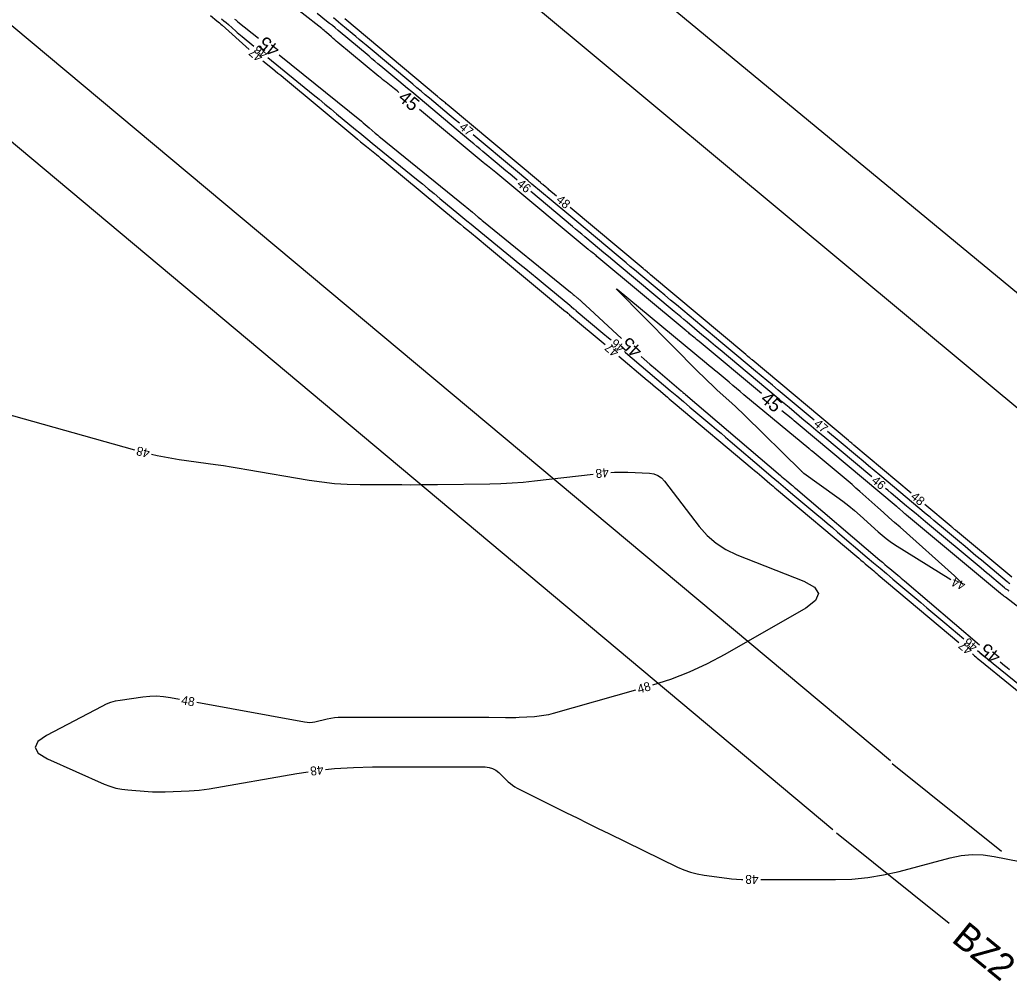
# Model space of a CAD drawing. Extents: x 2384780 to 2405861, y 547869 to 573706.
# Drawn here: x 2392529.2 to 2392751.8, y 552907.6 to 553123.7 of the extents above; entities that cross this region are included whole.
import ezdxf

# ---------------------------------------------------------------- set-up
doc = ezdxf.new("R2010")
doc.units = 0
for name, color, linetype in [('Old_Level_60', 7, 'Continuous'), ('Old_Level_61', 7, 'Continuous'), ('Prop Buffer Zone 1', 7, 'Continuous'), ('Prop Buffer Zone 2', 7, 'Continuous')]:
    doc.layers.add(name, color=color, linetype=linetype)

msp = doc.modelspace()

# ---------------------------------------------------------------- linework, layer by layer
at = {"layer": 'Old_Level_60'}
for points in [[(2392572.113, 553124.66375), (2392573.5235, 553123.49125), (2392573.8245, 553123.2385), (2392574.1235, 553122.9835), (2392574.42025, 553122.72575), (2392574.7145, 553122.4655), (2392580.7955, 553117.043), (2392580.8155, 553117.02525)], [(2392574.6105, 553123.9415), (2392575.1245, 553123.5025), (2392575.63475, 553123.05925), (2392576.14125, 553122.61175), (2392577.7895, 553121.142), (2392578.14425, 553120.829), (2392578.50275, 553120.52025), (2392578.8645, 553120.2155), (2392579.23, 553119.91475), (2392581.874, 553117.76375)], [(2392641.1105, 553087.631), (2392640.4955, 553088.145), (2392639.51825, 553088.96175), (2392638.54125, 553089.7785), (2392637.5645, 553090.59575), (2392636.588, 553091.413), (2392633.39775, 553094.08325), (2392632.714, 553094.65525), (2392632.03025, 553095.22725), (2392631.3465, 553095.79925), (2392630.6625, 553096.37075), (2392617.3725, 553107.4775), (2392616.41825, 553108.27525), (2392615.464, 553109.073), (2392614.51, 553109.871), (2392613.55625, 553110.66925), (2392610.4405, 553113.27725), (2392609.77275, 553113.836), (2392609.105, 553114.3945), (2392608.437, 553114.953), (2392607.769, 553115.5115), (2392600.80925, 553121.32775), (2392600.17225, 553121.85675), (2392599.532, 553122.382), (2392598.88875, 553122.9035), (2392598.24225, 553123.421), (2392596.12525, 553125.10525)], [(2392628.10725, 553100.43), (2392627.137, 553101.2415), (2392625.787, 553102.36975), (2392621.3765, 553106.05575), (2392620.4315, 553106.84575), (2392619.4865, 553107.636), (2392618.54175, 553108.42625), (2392617.59725, 553109.21675), (2392607.14, 553117.96925), (2392606.3545, 553118.6265), (2392605.56875, 553119.28375), (2392604.783, 553119.941), (2392603.99725, 553120.59775), (2392601.42975, 553122.7435), (2392600.878, 553123.2015), (2392600.32375, 553123.6565), (2392599.76675, 553124.10775)], [(2392649.97075, 553084.05325), (2392648.23725, 553085.504), (2392648.04625, 553085.664), (2392647.855, 553085.824), (2392647.66375, 553085.98375), (2392647.4725, 553086.14375), (2392646.84775, 553086.666), (2392646.71375, 553086.77775), (2392646.58, 553086.88975), (2392646.446, 553087.00175), (2392646.31225, 553087.11375), (2392625.3745, 553104.6385), (2392625.1595, 553104.81875), (2392624.94425, 553104.99875), (2392624.729, 553105.17875), (2392624.5135, 553105.35875), (2392623.81025, 553105.9465), (2392623.6595, 553106.0725), (2392623.50875, 553106.1985), (2392623.35825, 553106.3245), (2392623.2075, 553106.4505), (2392602.30675, 553123.94425)], [(2392584.97675, 553115.2395), (2392595.2065, 553106.9175), (2392596.52775, 553105.84), (2392597.84625, 553104.759), (2392599.16225, 553103.67475), (2392600.47525, 553102.58725), (2392604.7605, 553099.0295), (2392605.67975, 553098.26825), (2392606.60075, 553097.50925), (2392607.524, 553096.75275), (2392608.44875, 553095.99825), (2392618.4575, 553087.8565), (2392619.77275, 553086.784), (2392621.0855, 553085.70775), (2392622.3955, 553084.6285), (2392623.70275, 553083.546), (2392627.9685, 553080.004), (2392628.8835, 553079.24625), (2392629.8005, 553078.49075), (2392630.7195, 553077.7375), (2392631.64025, 553076.98675), (2392641.70975, 553068.796), (2392643.019, 553067.72825), (2392644.32575, 553066.65725), (2392645.62975, 553065.58275), (2392646.931, 553064.50525), (2392652.93825, 553059.51725), (2392652.96775, 553059.49275), (2392652.997, 553059.46825), (2392653.02625, 553059.44375), (2392653.0555, 553059.41925), (2392653.151, 553059.339), (2392653.1715, 553059.322), (2392653.19175, 553059.30475), (2392653.21225, 553059.28725), (2392653.2325, 553059.27), (2392653.86075, 553058.733), (2392653.9955, 553058.618), (2392654.1305, 553058.5035), (2392654.26575, 553058.389), (2392654.40125, 553058.275), (2392660.37625, 553053.25575), (2392661.6555, 553052.179), (2392662.20525, 553051.7145)], [(2392583.902, 553114.48125), (2392586.02125, 553112.757), (2392586.649, 553112.245), (2392587.2755, 553111.7315), (2392587.90075, 553111.21625), (2392588.52475, 553110.6995), (2392604.5465, 553097.3975), (2392605.21675, 553096.84225), (2392605.8885, 553096.28875), (2392606.5615, 553095.737), (2392607.236, 553095.187), (2392609.44175, 553093.39275), (2392609.914, 553093.00775), (2392610.385, 553092.6215), (2392610.85525, 553092.234), (2392611.3245, 553091.8455), (2392627.66775, 553078.276), (2392628.33675, 553077.722), (2392629.007, 553077.16975), (2392629.6785, 553076.61925), (2392630.3515, 553076.07025), (2392632.5525, 553074.28025), (2392633.0235, 553073.896), (2392633.49375, 553073.5105), (2392633.96275, 553073.124), (2392634.431, 553072.73625), (2392651.996, 553058.152), (2392652.05925, 553058.0995), (2392652.12225, 553058.047), (2392652.18525, 553057.99425), (2392652.248, 553057.9415), (2392652.454, 553057.7685), (2392652.4975, 553057.73175), (2392652.541, 553057.695), (2392652.5845, 553057.65825), (2392652.62775, 553057.62125), (2392652.769, 553057.5005), (2392652.79925, 553057.47475), (2392652.8295, 553057.449), (2392652.86, 553057.42325), (2392652.8905, 553057.39775), (2392660.89675, 553050.672)], [(2392707.87475, 553033.69825), (2392699.7985, 553040.45825), (2392698.5195, 553041.52875), (2392697.24, 553042.599), (2392695.9605, 553043.66875), (2392694.68075, 553044.7385), (2392690.50025, 553048.2325), (2392689.60425, 553048.9815), (2392688.70875, 553049.73025), (2392687.81325, 553050.4795), (2392686.91775, 553051.22875), (2392676.928, 553059.5905), (2392675.6255, 553060.6805), (2392674.32275, 553061.77025), (2392673.01975, 553062.86), (2392671.7165, 553063.94925), (2392667.459, 553067.50725), (2392666.54675, 553068.26975), (2392665.63475, 553069.0325), (2392664.72275, 553069.79525), (2392663.811, 553070.5585), (2392654.05725, 553078.7225), (2392652.73125, 553079.83225), (2392651.405, 553080.9415), (2392650.0785, 553082.05075), (2392648.752, 553083.15975), (2392644.418, 553086.78175), (2392643.48925, 553087.558), (2392642.56075, 553088.33425), (2392641.6325, 553089.111), (2392640.70425, 553089.88775), (2392631.186, 553097.8545), (2392631.17525, 553097.8635)], [(2392720.89825, 553020.92325), (2392709.8635, 553030.14525), (2392708.818, 553031.0195), (2392707.7725, 553031.8935), (2392706.72725, 553032.768), (2392705.682, 553033.64275), (2392702.26825, 553036.5), (2392701.53675, 553037.11225), (2392700.805, 553037.7245), (2392700.07325, 553038.3365), (2392699.34125, 553038.94825), (2392686.741, 553049.47875), (2392685.71825, 553050.33375), (2392684.6955, 553051.189), (2392683.67325, 553052.04425), (2392682.65075, 553052.89975), (2392679.31175, 553055.69475), (2392678.596, 553056.2935), (2392677.8805, 553056.89225), (2392677.1645, 553057.49075), (2392676.44875, 553058.08925), (2392663.61825, 553068.812), (2392662.61825, 553069.648), (2392661.6185, 553070.484), (2392660.619, 553071.32), (2392659.6195, 553072.1565), (2392656.35475, 553074.889), (2392655.65525, 553075.4745), (2392654.9555, 553076.05975), (2392654.25575, 553076.645), (2392653.55575, 553077.23), (2392644.17975, 553085.06575)], [(2392729.72275, 553017.30275), (2392716.8235, 553028.09975), (2392716.7045, 553028.19925), (2392716.5855, 553028.29875), (2392716.46675, 553028.39825), (2392716.3475, 553028.49775), (2392715.95875, 553028.82275), (2392715.8755, 553028.89225), (2392715.79225, 553028.962), (2392715.709, 553029.03175), (2392715.62575, 553029.10125), (2392693.96175, 553047.2345), (2392693.81875, 553047.35425), (2392693.67575, 553047.474), (2392693.5325, 553047.59375), (2392693.3895, 553047.71325), (2392692.922, 553048.104), (2392692.82175, 553048.18775), (2392692.7215, 553048.2715), (2392692.6215, 553048.35525), (2392692.52125, 553048.43925), (2392671.09975, 553066.36925), (2392670.93275, 553066.50925), (2392670.7655, 553066.649), (2392670.59825, 553066.78875), (2392670.431, 553066.9285), (2392669.88475, 553067.38525), (2392669.76775, 553067.483), (2392669.65075, 553067.58075), (2392669.53375, 553067.67875), (2392669.41675, 553067.7765), (2392653.038, 553081.48575)], [(2392741.396, 552996.756), (2392741.228, 552997.003), (2392739.46225, 552998.67075), (2392727.218, 553009.59675), (2392725.9755, 553010.7055), (2392724.733, 553011.81425), (2392723.4905, 553012.923), (2392722.248, 553014.03175), (2392718.189, 553017.6535), (2392717.316, 553018.426), (2392716.43675, 553019.19125), (2392715.55125, 553019.949), (2392714.65925, 553020.6995), (2392707.456, 553026.71025), (2392707.384, 553026.77025), (2392707.312, 553026.83), (2392707.24, 553026.89), (2392707.16775, 553026.94975), (2392706.93225, 553027.14475), (2392706.88175, 553027.18675), (2392706.83125, 553027.2285), (2392706.78075, 553027.27025), (2392706.73025, 553027.312), (2392692.10825, 553039.42125), (2392691.273, 553040.1135), (2392690.43825, 553040.80675), (2392689.60425, 553041.5005), (2392688.771, 553042.19525), (2392686.04975, 553044.46575), (2392685.46625, 553044.95175), (2392684.88225, 553045.4375), (2392684.29775, 553045.92225), (2392683.71275, 553046.4065), (2392663.59025, 553063.03825), (2392663.587, 553063.04075), (2392663.584, 553063.0435), (2392663.58075, 553063.046), (2392663.57775, 553063.0485), (2392663.5675, 553063.05725), (2392663.56525, 553063.059), (2392663.563, 553063.06075), (2392663.56075, 553063.0625), (2392663.55875, 553063.06425), (2392663.42125, 553063.1725), (2392663.399, 553063.18975), (2392663.3915, 553063.195), (2392663.39825, 553063.1885), (2392663.4195, 553063.17025)], [(2392663.4195, 553063.17025), (2392663.559, 553063.05125), (2392663.55925, 553063.051), (2392663.55925, 553063.051), (2392663.5595, 553063.05075), (2392663.55975, 553063.0505), (2392663.56025, 553063.05), (2392663.5605, 553063.05), (2392663.5605, 553063.04975), (2392663.56075, 553063.04975), (2392663.56075, 553063.0495), (2392663.577, 553063.03475), (2392663.58025, 553063.0315), (2392663.58375, 553063.02825), (2392663.587, 553063.025), (2392663.5905, 553063.02175), (2392681.99425, 553044.393), (2392682.987, 553043.40275), (2392683.9935, 553042.427), (2392685.014, 553041.466), (2392686.0485, 553040.51975), (2392689.45075, 553037.452), (2392690.17625, 553036.79075), (2392690.89425, 553036.12175), (2392691.60475, 553035.445), (2392692.308, 553034.76025), (2392704.95075, 553022.3175), (2392705.0095, 553022.25975), (2392705.068, 553022.202), (2392705.12675, 553022.14425), (2392705.18525, 553022.0865), (2392705.377, 553021.898), (2392705.41875, 553021.8585), (2392705.462, 553021.82075), (2392705.50675, 553021.78475), (2392705.553, 553021.75075), (2392713.0355, 553016.46075), (2392714.387, 553015.4735), (2392715.70575, 553014.446), (2392716.99225, 553013.37775), (2392718.246, 553012.269), (2392722.2885, 553008.5815), (2392723.17075, 553007.8125), (2392724.08525, 553007.086), (2392725.032, 553006.402), (2392726.011, 553005.7605), (2392738.65725, 552997.8765)], [(2392665.25475, 553049.12575), (2392665.4805, 553048.9335), (2392674.00475, 553041.657), (2392675.49275, 553040.38975), (2392676.983, 553039.12525), (2392678.47575, 553037.86375), (2392679.97125, 553036.60525), (2392684.86, 553032.499), (2392685.907, 553031.618), (2392686.952, 553030.73525), (2392687.9955, 553029.8505), (2392689.0375, 553028.96375), (2392696.602, 553022.51425), (2392698.22425, 553021.1335), (2392699.84925, 553019.756), (2392701.4765, 553018.38175), (2392703.1065, 553017.01025), (2392708.52475, 553012.46025), (2392709.68475, 553011.48425), (2392710.84325, 553010.506), (2392712, 553009.526), (2392713.15525, 553008.544), (2392719.854, 553002.838), (2392721.29075, 553001.61675), (2392722.72925, 553000.39775), (2392724.17025, 552999.1815), (2392725.61325, 552997.9675), (2392731.92725, 552992.666), (2392733.27925, 552991.52875), (2392734.6295, 552990.38925), (2392735.97775, 552989.24775), (2392737.32425, 552988.10375), (2392741.563, 552984.49675)], [(2392663.9595, 553048.099), (2392670.36525, 553042.718), (2392670.99025, 553042.19175), (2392671.61425, 553041.6645), (2392672.23725, 553041.13575), (2392672.85925, 553040.606), (2392674.8895, 553038.873), (2392675.32475, 553038.502), (2392675.761, 553038.132), (2392676.19775, 553037.763), (2392676.6355, 553037.3945), (2392693.9575, 553022.84575), (2392694.50675, 553022.3835), (2392695.055, 553021.9205), (2392695.6025, 553021.45625), (2392696.149, 553020.99125), (2392697.933, 553019.47), (2392698.31575, 553019.1445), (2392698.699, 553018.8195), (2392699.08275, 553018.4955), (2392699.46725, 553018.172), (2392717.47575, 553003.04875), (2392717.9585, 553002.64275), (2392718.44025, 553002.23575), (2392718.9215, 553001.82825), (2392719.402, 553001.41975), (2392720.97025, 553000.08375), (2392721.30675, 552999.79775), (2392721.6435, 552999.5125), (2392721.98075, 552999.22775), (2392722.31875, 552998.9435), (2392740.46675, 552983.705)], [(2392525.41825, 553035.3715), (2392554.98525, 553027.0115)], [(2392751.8935, 552996.914), (2392751.70325, 552997.051), (2392751.51725, 552997.1935), (2392751.33525, 552997.3415), (2392745.5385, 553002.19375), (2392744.30625, 553003.22475), (2392743.074, 553004.25575), (2392741.8415, 553005.28625), (2392740.60875, 553006.31675), (2392736.58175, 553009.6825), (2392735.71875, 553010.40375), (2392734.856, 553011.12525), (2392733.9935, 553011.84675), (2392733.131, 553012.5685), (2392722.66875, 553021.326), (2392721.413, 553022.37675), (2392720.15725, 553023.42725), (2392718.90125, 553024.47775), (2392717.645, 553025.52775), (2392713.541, 553028.95775), (2392712.66175, 553029.69275), (2392711.7825, 553030.428), (2392710.94225, 553031.13075)], [(2392558.86175, 553026.0275), (2392560.0825, 553025.7485), (2392562.56625, 553025.269), (2392565.0675, 553024.8735), (2392573.2675, 553023.719), (2392575.02375, 553023.465), (2392576.77775, 553023.198), (2392578.52975, 553022.91775), (2392580.27975, 553022.6245), (2392594.3275, 553020.21675), (2392597.169, 553019.79025), (2392600.02075, 553019.48225), (2392602.88275, 553019.2935), (2392605.755, 553019.2235), (2392615.155, 553019.18875), (2392617.16925, 553019.18575), (2392619.1835, 553019.1915), (2392621.19775, 553019.206), (2392623.21175, 553019.22925), (2392634.943, 553019.3905), (2392637.45475, 553019.45675), (2392639.9625, 553019.58625), (2392642.466, 553019.77925), (2392644.96575, 553020.03575), (2392658.213, 553021.56375)], [(2392662.19325, 553021.9515), (2392662.998, 553021.99575), (2392664.49, 553022.018), (2392665.98375, 553021.9805), (2392670.86725, 553021.7605), (2392671.8625, 553021.6155), (2392672.7555, 553021.274), (2392673.546, 553020.7365), (2392674.234, 553020.003), (2392682.03875, 553009.81175), (2392683.82175, 553007.7745), (2392685.82625, 553006.03025), (2392688.05225, 553004.57925), (2392690.4995, 553003.4215), (2392705.563, 552997.4665), (2392708.011, 552996.13375), (2392708.89975, 552994.68825), (2392708.22875, 552993.1295), (2392705.9985, 552991.458), (2392687.7995, 552981.0095), (2392683.84675, 552978.89625), (2392679.788, 552977.034), (2392675.623, 552975.4225), (2392671.55875, 552974.12825)], [(2392751.785, 552995.25025), (2392751.6505, 552995.34425), (2392751.51425, 552995.43575), (2392751.066, 552995.73), (2392750.97075, 552995.7945), (2392750.87775, 552995.86175), (2392750.7865, 552995.9315), (2392750.6975, 552996.00375), (2392747.86675, 552998.37325), (2392747.26, 552998.881), (2392746.6535, 552999.3885), (2392746.0465, 552999.896), (2392745.43975, 553000.40325), (2392732.986, 553010.8115), (2392731.9175, 553011.70475), (2392730.84925, 553012.598), (2392729.781, 553013.4915), (2392728.71325, 553014.3855), (2392725.22475, 553017.3055), (2392724.477, 553017.931), (2392723.967, 553018.3575)], [(2392752.34825, 552998.36475), (2392739.685, 553008.96475), (2392739.59, 553009.044), (2392739.49525, 553009.1235), (2392739.40025, 553009.20275), (2392739.3055, 553009.282), (2392738.9955, 553009.541), (2392738.92925, 553009.5965), (2392738.86275, 553009.65225), (2392738.79625, 553009.70775), (2392738.73, 553009.76325), (2392732.79, 553014.73525)], [(2392744.614, 552981.91), (2392745.63075, 552981.05975), (2392746.89025, 552980.01925), (2392748.1555, 552978.986), (2392756.01225, 552972.608)], [(2392743.5205, 552981.1215), (2392744.0025, 552980.71125), (2392744.2985, 552980.46075), (2392744.59575, 552980.21225), (2392744.8945, 552979.96525), (2392745.19475, 552979.72), (2392765.6355, 552963.1265)], [(2392667.71425, 552973.02375), (2392649.216, 552967.7415), (2392648.17925, 552967.4755), (2392647.1325, 552967.267), (2392646.076, 552967.116), (2392645.00975, 552967.02225), (2392641.51025, 552966.81025), (2392640.76025, 552966.77225), (2392640.01, 552966.74925), (2392639.25925, 552966.741), (2392638.5085, 552966.7475), (2392634.75925, 552966.8175), (2392633.956, 552966.8305), (2392633.1525, 552966.84), (2392632.349, 552966.8455), (2392631.5455, 552966.8475), (2392601.70975, 552966.8475), (2392600.85775, 552966.823), (2392600.01125, 552966.75), (2392599.1705, 552966.62825), (2392598.33525, 552966.458), (2392595.616, 552965.822), (2392595.03275, 552965.716), (2392594.44775, 552965.67125), (2392593.86125, 552965.6875), (2392593.2735, 552965.76475), (2392569.05325, 552970.199)], [(2392565.11875, 552970.91925), (2392563.10225, 552971.2885), (2392561.55, 552971.509), (2392559.995, 552971.603), (2392558.43775, 552971.5705), (2392556.87775, 552971.411), (2392551.778, 552970.68375), (2392550.7, 552970.483), (2392549.65075, 552970.19225), (2392548.63075, 552969.812), (2392547.64, 552969.34175), (2392535.2465, 552962.8025), (2392533.26575, 552961.424), (2392532.635, 552960.091), (2392533.354, 552958.80375), (2392535.42325, 552957.56175), (2392548.2095, 552951.8815), (2392549.49525, 552951.37475), (2392550.81, 552950.984), (2392552.154, 552950.7095), (2392553.52675, 552950.55075), (2392558.059, 552950.22225), (2392559.03025, 552950.1655), (2392560.00225, 552950.1355), (2392560.9745, 552950.1325), (2392561.94725, 552950.15675), (2392567.27925, 552950.3625), (2392568.41975, 552950.4255), (2392569.5565, 552950.52625), (2392570.689, 552950.6645), (2392571.81775, 552950.84075), (2392591.545, 552954.2535), (2392594.0485, 552954.63175)], [(2392598.016, 552955.13375), (2392600.03075, 552955.3505), (2392604.29725, 552955.62475), (2392608.5795, 552955.716), (2392633.91025, 552955.716), (2392634.77725, 552955.63775), (2392635.5805, 552955.40225), (2392636.32, 552955.01), (2392636.99575, 552954.461), (2392639.09875, 552952.411), (2392639.5635, 552951.9915), (2392640.056, 552951.6115), (2392640.577, 552951.27075), (2392641.12575, 552950.96975), (2392652.19225, 552945.4365), (2392654.565, 552944.254), (2392656.94125, 552943.07825), (2392659.32075, 552941.909), (2392661.7035, 552940.7465), (2392677.15725, 552933.23275), (2392678.59675, 552932.6015), (2392680.0725, 552932.09025), (2392681.5845, 552931.69925), (2392683.13275, 552931.428), (2392688.2495, 552930.738), (2392689.347, 552930.6085), (2392690.44725, 552930.51525), (2392691.55, 552930.45875), (2392691.88075, 552930.45275)], [(2392695.8805, 552930.433), (2392712.737, 552930.40425), (2392716.35525, 552930.51475), (2392719.9435, 552930.85875), (2392723.5015, 552931.43625), (2392727.0295, 552932.2475), (2392738.522, 552935.283), (2392740.97675, 552935.788), (2392743.44075, 552936.00875), (2392745.91375, 552935.94525), (2392748.396, 552935.5975), (2392757.25725, 552933.85175)]]:
    msp.add_lwpolyline(points, dxfattribs=at)
at = {"layer": 'Old_Level_61'}
for points in [[(2392614.507, 553107.3885), (2392614.10275, 553107.7105), (2392613.52, 553108.16675), (2392611.60925, 553109.64875), (2392611.20125, 553109.968), (2392610.796, 553110.29075), (2392610.3935, 553110.617), (2392609.99375, 553110.9465), (2392600.7815, 553118.6075), (2392600.4175, 553118.9125), (2392600.056, 553119.2205), (2392599.69675, 553119.53125), (2392599.33975, 553119.84475), (2392598.178, 553120.8735), (2392597.9275, 553121.092), (2392597.67375, 553121.30675), (2392597.417, 553121.51775), (2392597.157, 553121.725), (2392579.43625, 553135.644)], [(2392577.53275, 553123.8665), (2392577.784, 553123.67175), (2392578.0335, 553123.47475), (2392578.28125, 553123.27575), (2392582.8745, 553119.55425)], [(2392587.58675, 553115.84125), (2392606.04475, 553100.8935), (2392606.481, 553100.53725), (2392606.9145, 553100.17775), (2392607.345, 553099.81475), (2392607.77275, 553099.44825), (2392609.1655, 553098.24575), (2392609.46475, 553097.98925), (2392609.76625, 553097.73525), (2392610.0695, 553097.48325), (2392610.375, 553097.234), (2392629.38825, 553081.8275), (2392629.80125, 553081.4905), (2392630.2115, 553081.15075), (2392630.61975, 553080.80825), (2392631.0255, 553080.463), (2392632.347, 553079.33), (2392632.631, 553079.08825), (2392632.9165, 553078.8485), (2392633.20375, 553078.61075), (2392633.49275, 553078.37475), (2392653.0845, 553062.49225), (2392653.295, 553062.3205), (2392653.5045, 553062.1475), (2392653.713, 553061.97325), (2392653.9205, 553061.7975), (2392654.596, 553061.22175), (2392654.74025, 553061.0975), (2392654.88325, 553060.97225), (2392655.025, 553060.8455), (2392655.16575, 553060.7175), (2392655.854, 553060.08475), (2392656.0015, 553059.949), (2392656.149, 553059.8135), (2392656.29675, 553059.67775), (2392656.44425, 553059.54225), (2392664.57975, 553052.064)], [(2392696.047, 553039.66275), (2392682.006, 553051.37775), (2392681.71675, 553051.61875), (2392681.4275, 553051.8595), (2392681.13775, 553052.09975), (2392680.84775, 553052.3395), (2392679.9, 553053.123), (2392679.69725, 553053.29075), (2392679.49425, 553053.459), (2392679.29175, 553053.6275), (2392679.08925, 553053.79625), (2392659.0495, 553070.51375), (2392658.8575, 553070.6725), (2392658.66475, 553070.83), (2392658.47075, 553070.986), (2392658.2755, 553071.14075), (2392657.6365, 553071.644), (2392657.49975, 553071.75225), (2392657.364, 553071.8615), (2392657.229, 553071.97175), (2392657.09475, 553072.083), (2392638.12275, 553087.90125), (2392637.6675, 553088.278), (2392637.209, 553088.651), (2392636.748, 553089.0205), (2392636.28375, 553089.38625), (2392634.763, 553090.5755), (2392634.43825, 553090.8315), (2392634.11525, 553091.09), (2392633.7945, 553091.35125), (2392633.4755, 553091.61475), (2392619.12875, 553103.5625)], [(2392669.00975, 553048.0175), (2392669.67375, 553047.42375), (2392670.94, 553046.3125), (2392672.21625, 553045.21275), (2392678.00025, 553040.2755), (2392678.0985, 553040.192), (2392678.19675, 553040.1085), (2392678.295, 553040.0255), (2392678.39375, 553039.9425), (2392678.716, 553039.67175), (2392678.785, 553039.61375), (2392678.85375, 553039.5555), (2392678.9225, 553039.49725), (2392678.99125, 553039.43875), (2392700.31625, 553021.25675), (2392700.6535, 553020.9695), (2392700.99125, 553020.68325), (2392701.32975, 553020.39725), (2392701.66875, 553020.11225), (2392702.777, 553019.1815), (2392703.01425, 553018.982), (2392703.251, 553018.782), (2392703.48775, 553018.5815), (2392703.724, 553018.3805), (2392722.711, 553002.20825), (2392723.25975, 553001.74175), (2392723.80925, 553001.276), (2392724.35975, 553000.8115), (2392724.911, 553000.34775), (2392726.71325, 552998.8345), (2392727.099, 552998.51), (2392727.4845, 552998.18475), (2392727.86925, 552997.85875), (2392728.2535, 552997.5325), (2392745.11575, 552983.18275), (2392745.13175, 552983.16925)], [(2392772.9995, 552976.882), (2392750.9205, 552993.864), (2392750.8095, 552993.94975), (2392750.6985, 552994.0355), (2392750.588, 552994.1215), (2392750.4775, 552994.20775), (2392750.11675, 552994.48975), (2392750.03975, 552994.5505), (2392749.963, 552994.61175), (2392749.887, 552994.67375), (2392749.81125, 552994.73625), (2392728.71, 553012.31175), (2392728.50325, 553012.48575), (2392728.29775, 553012.66125), (2392728.09375, 553012.8385), (2392727.8915, 553013.0175), (2392727.0925, 553013.7305), (2392727.0215, 553013.794), (2392726.9505, 553013.85725), (2392726.8795, 553013.92075), (2392726.8085, 553013.984), (2392726.5765, 553014.191), (2392726.5265, 553014.23525), (2392726.47625, 553014.279), (2392726.42575, 553014.32225), (2392726.37475, 553014.36525), (2392704.3345, 553032.756), (2392704.329, 553032.7605), (2392704.32375, 553032.765), (2392704.3185, 553032.7695), (2392704.313, 553032.77375), (2392704.2955, 553032.78825), (2392704.29175, 553032.7915), (2392704.288, 553032.7945), (2392704.28425, 553032.79775), (2392704.2805, 553032.80075), (2392703.43325, 553033.5025), (2392703.25175, 553033.65275), (2392703.0705, 553033.8035), (2392702.88925, 553033.95425), (2392702.70825, 553034.10525), (2392700.65425, 553035.819)], [(2392749.76075, 552979.352), (2392750.7485, 552978.55025), (2392751.2945, 552978.108), (2392751.84125, 552977.6665)]]:
    msp.add_lwpolyline(points, dxfattribs=at)
at = {"layer": 'Prop Buffer Zone 1'}
for points in [[(2392529.4375, 553221.34725), (2392588.6105, 553173.8495), (2392771.6345, 553021.47725)], [(2392725.094, 552957.06675), (2392484.20575, 553158.46475)], [(2392725.469, 552956.51925), (2392750.017, 552936.82875)]]:
    msp.add_lwpolyline(points, dxfattribs=at)
at = {"layer": 'Prop Buffer Zone 2'}
for points in [[(2392542.609, 553236.42075), (2392786.472, 553035.20425)], [(2392712.13125, 552941.593), (2392471.7935, 553142.773)], [(2392712.955, 552940.918), (2392738.24525, 552920.63225)]]:
    msp.add_lwpolyline(points, dxfattribs=at)

# ---------------------------------------------------------------- texts
at = {"layer": 'Old_Level_60'}
for s, rotation, p in [('46', 140.8708444, (2392585.20475, 553116.34325)), ('47', 140.5023028, (2392584.09225, 553115.6035)), ('47', 320.0834861, (2392627.90075, 553099.2995)), ('46', 320.1136472, (2392640.868, 553086.53025)), ('48', 320.0703333, (2392649.7095, 553082.96775)), ('47', 139.9680639, (2392664.1685, 553049.2295)), ('46', 139.6734944, (2392665.507, 553050.22625)), ('47', 320.071475, (2392707.66775, 553032.56725)), ('48', 165.7563778, (2392558.6215, 553027.09625)), ('48', 185.5645833, (2392661.6, 553022.93025)), ('46', 320.1054222, (2392720.65575, 553019.82275)), ('48', 320.069425, (2392729.46125, 553016.21725)), ('44', 157.7493889, (2392742.13, 552997.228)), ('46', 139.708775, (2392744.862, 552983.006)), ('47', 139.7649472, (2392743.7365, 552982.2545)), ('48', 16.0303556, (2392668.46825, 552972.1965)), ('48', 349.6253556, (2392565.42675, 552969.84625)), ('48', 187.211975, (2392597.39375, 552956.10075)), ('48', 179.7187417, (2392695.38925, 552931.429))]:
    msp.add_text(s, height=2, rotation=rotation, dxfattribs=at).set_placement(p)
at = {"layer": 'Old_Level_61'}
for rotation, p in [(141.7617778, (2392587.9535, 553117.432)), (320.3813611, (2392614.093, 553105.7955)), (137.5892889, (2392669.5005, 553049.588)), (320.1604028, (2392695.62125, 553038.0645)), (140.4904444, (2392750.1645, 552980.93725))]:
    msp.add_text('45', height=3, rotation=rotation, dxfattribs=at).set_placement(p)
at = {"layer": 'Prop Buffer Zone 2'}
msp.add_text('BZ2', height=6, rotation=320.7836639, dxfattribs=at).set_placement((2392738.56375, 552916.6075))

doc.saveas('drawing.dxf')
